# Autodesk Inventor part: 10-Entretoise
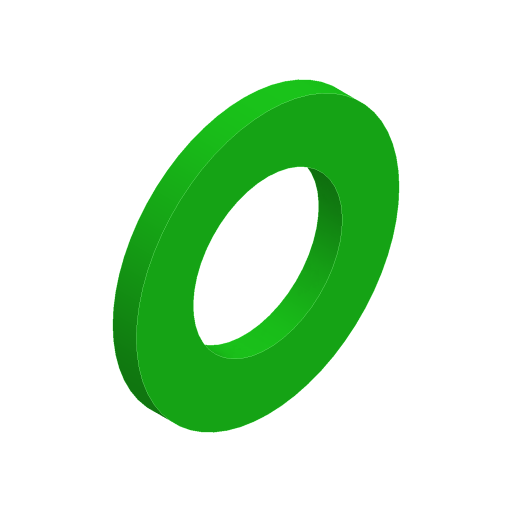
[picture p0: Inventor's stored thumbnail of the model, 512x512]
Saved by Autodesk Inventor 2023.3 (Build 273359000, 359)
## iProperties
Created: 2023-12
Part Number: 10-Entretoise
Material: Générique
Document SubType Name: Modeling
Designer: Thier
Density: 1 g/cm^3
Appearance: Vert foncé
Author: Thier
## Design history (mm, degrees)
sketch "Esquisse1"
  geometry: C1 r 8.5 at (0, 0); C2 r 15 at (0, 0); 1 further point
  constraints: 2 centre point, 2 coincident
  dimensions: "d0" = 30 diameter of C2; "d1" = 17 diameter of C1
extrude "Extrusion1" new body sketch "Esquisse1" distance "d2" = 2.7; taper "d3" = 0 deg
node "Solide1"
